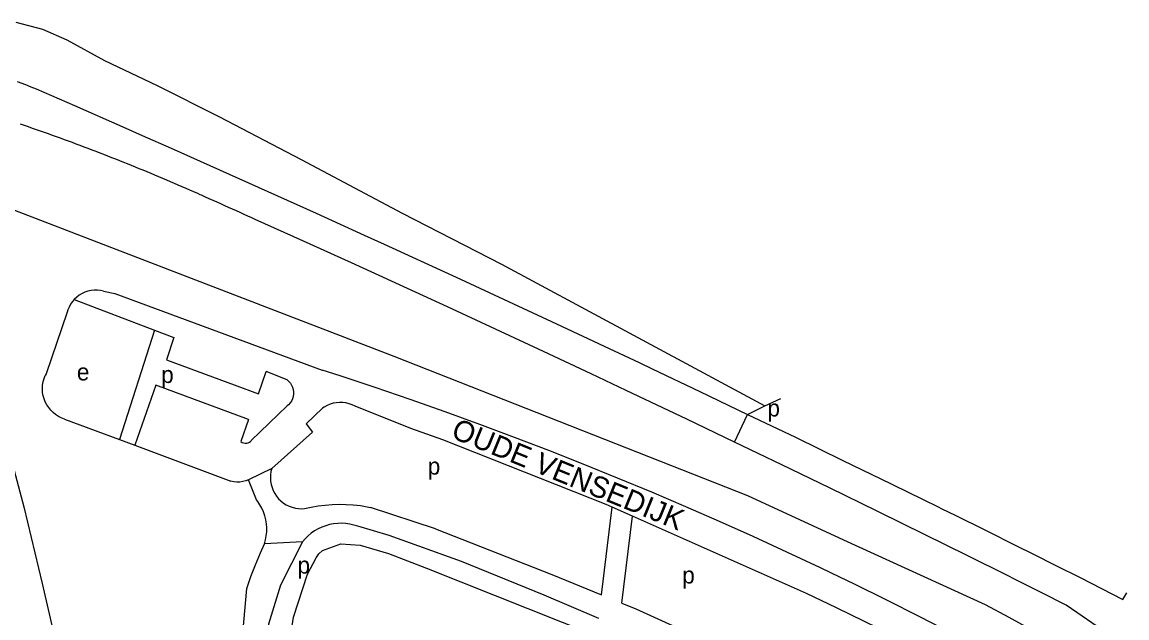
# Model space of a CAD drawing. Extents: x 157569 to 159501, y 382907 to 384670.
# Drawn here: x 157822.4 to 158083.4, y 384391.1 to 384531.9 of the extents above; entities that cross this region are included whole.
import ezdxf

# ---------------------------------------------------------------- set-up
doc = ezdxf.new("R2010")
doc.units = 0
for name, color, linetype in [('BLT_Basislijn', 7, 'Continuous'), ('BLT_Centroide', 7, 'Continuous'), ('BLT_Straatnaam', 7, 'Continuous'), ('BLT_Vlakafsluiter', 7, 'Continuous')]:
    doc.layers.add(name, color=color, linetype=linetype)

msp = doc.modelspace()

# ---------------------------------------------------------------- linework, layer by layer
at = {"layer": 'BLT_Basislijn'}
for p, q in [((157834.75, 384466.32), (157853.74, 384459.06)), ((157833.07, 384463.36), (157828.09, 384448.73)), ((157853.74, 384459.06), (157845.4, 384433.23)), ((157885.02, 384447.33), (157880.1, 384449.33)), ((157828.09, 384448.73), (157827.88, 384448.33)), ((157876.54, 384432.99), (157885.07, 384441.18)), ((157914.28, 384435.88), (157901.1, 384441.13)), ((157832.41, 384438.07), (157845.4, 384433.23)), ((157875.9, 384437.95), (157874.14, 384432.77)), ((157845.4, 384433.23), (157849.02, 384431.88)), ((157849.02, 384431.88), (157871.73, 384423.42)), ((157881.4, 384426.41), (157875.92, 384423.71)), ((157877.79, 384419.02), (157875.92, 384423.71)), ((157920.13, 384412.11), (157904.71, 384417.21)), ((157959.33, 384396.56), (157961.83, 384417.29)), ((157964.13, 384394.6), (157966.61, 384415.16)), ((157892.54, 384406.25), (157893.39, 384407.05)), ((157893.39, 384407.05), (157897.72, 384408.6)), ((157897.72, 384408.6), (157902.31, 384408.32)), ((157902.31, 384408.32), (157909.02, 384406.29)), ((157889.87, 384401.46), (157891.87, 384405.29)), ((157891.87, 384405.29), (157892.54, 384406.25)), ((157909.02, 384406.29), (157917.97, 384402.83)), ((157917.97, 384402.83), (157958.16, 384386.84)), ((157886.51, 384391.25), (157889.87, 384401.46)), ((157884.93, 384380.62), (157886.51, 384391.25))]:
    msp.add_line(p, q, dxfattribs=at)
for points in [[(157820.98, 384531.86), (157827.21, 384530.17), (157832.97, 384527.64), (157841.86, 384522.76), (157854.32, 384516.88), (157869.04, 384509.47), (157888.36, 384499.41), (157912.21, 384486.72), (157935.72, 384474.64), (157954.45, 384464.62), (157997.88, 384441.21)], [(157821.29, 384517.79), (157823.26, 384517.08), (157824.5, 384516.6), (157825.73, 384516.08), (157834.77, 384512.14), (157846.21, 384507.11), (157850.77, 384505.1), (157857.65, 384502.06), (157869.07, 384496.97), (157880.48, 384491.86), (157891.87, 384486.72), (157903.26, 384481.55), (157907.94, 384479.42), (157914.62, 384476.36), (157925.98, 384471.13), (157937.33, 384465.88), (157948.66, 384460.6), (157959.97, 384455.29), (157968.21, 384451.4), (157971.28, 384449.95), (157982.57, 384444.58), (157993.84, 384439.19)], [(157990.71, 384432.65), (157979.45, 384438.04), (157968.17, 384443.4), (157965.11, 384444.85), (157956.89, 384448.73), (157945.58, 384454.03), (157934.27, 384459.3), (157922.94, 384464.55), (157911.6, 384469.77), (157904.93, 384472.82), (157900.25, 384474.96), (157888.88, 384480.12), (157877.5, 384485.25), (157876.69, 384485.62), (157875.78, 384486.03), (157874.86, 384486.44), (157873.95, 384486.85), (157873.04, 384487.25), (157872.13, 384487.66), (157871.21, 384488.07), (157870.3, 384488.48), (157869.39, 384488.89), (157868.48, 384489.3), (157867.56, 384489.71), (157866.65, 384490.11), (157865.74, 384490.52), (157864.82, 384490.93), (157864.53, 384491.06), (157863.91, 384491.34), (157863, 384491.74), (157862.08, 384492.14), (157861.17, 384492.55), (157860.25, 384492.94), (157859.33, 384493.34), (157858.42, 384493.74), (157857.5, 384494.13), (157856.58, 384494.52), (157855.66, 384494.91), (157854.74, 384495.3), (157853.82, 384495.69), (157852.9, 384496.07), (157851.97, 384496.46), (157851.05, 384496.84), (157850.12, 384497.22), (157849.2, 384497.59), (157848.27, 384497.97), (157847.35, 384498.34), (157846.42, 384498.72), (157845.49, 384499.09), (157844.56, 384499.45), (157843.63, 384499.82), (157842.7, 384500.18), (157841.77, 384500.55), (157840.84, 384500.91), (157839.91, 384501.27), (157838.97, 384501.62), (157838.04, 384501.98), (157837.1, 384502.33), (157836.17, 384502.68), (157835.23, 384503.03), (157834.3, 384503.38), (157833.36, 384503.73), (157832.42, 384504.07), (157831.48, 384504.41), (157830.54, 384504.75), (157829.6, 384505.09), (157828.66, 384505.43), (157827.72, 384505.76), (157826.78, 384506.09), (157825.83, 384506.42), (157824.89, 384506.75), (157823.95, 384507.08), (157823, 384507.4), (157822.05, 384507.73)], [(158016.56, 384409.49), (157993.85, 384419.91), (157910.36, 384452.84), (157802.79, 384494.17)], [(157785.74, 384491.86), (157791.37, 384485.49), (157798.02, 384479.29), (157802.69, 384474.1), (157806.4, 384468.47), (157808.82, 384463.57), (157811.76, 384455.2), (157818.57, 384433.33), (157822.82, 384417.31), (157827.2, 384399.26), (157830.67, 384383.83), (157833.54, 384367.87), (157836.35, 384353.29), (157840.01, 384327.2), (157843.02, 384303.79), (157845.24, 384278.94), (157848.12, 384253.31), (157853.68, 384220.02), (157857.08, 384190.66), (157860.08, 384150.97), (157861.78, 384102.06), (157861.78, 384049.75), (157865.23, 384042.81)], [(157841.67, 384468.25), (157840.94, 384468.41), (157840.2, 384468.49), (157839.45, 384468.49), (157838.71, 384468.41), (157837.98, 384468.25), (157837.27, 384468.02), (157836.59, 384467.71), (157835.94, 384467.33), (157835.34, 384466.88), (157834.75, 384466.32)], [(157841.67, 384468.25), (157844.36, 384467.75), (157893.31, 384449.63)], [(157834.75, 384466.32), (157834.3, 384465.81), (157833.88, 384465.2), (157833.52, 384464.54), (157833.23, 384463.85), (157833.07, 384463.36)], [(157853.74, 384459.06), (157858.24, 384457.34), (157856.5, 384452.04), (157878.28, 384444.05), (157880.1, 384449.33)], [(158015.76, 384400.64), (158011.02, 384402.93), (158003.12, 384406.64), (157995.18, 384410.29), (157987.21, 384413.86), (157979.21, 384417.36), (157971.18, 384420.78), (157963.11, 384424.13), (157955.02, 384427.41), (157946.89, 384430.61), (157938.74, 384433.74), (157930.56, 384436.79), (157922.35, 384439.77), (157914.12, 384442.68), (157905.85, 384445.5), (157897.56, 384448.26), (157893.31, 384449.63)], [(157832.41, 384438.07), (157831.69, 384438.35), (157830.99, 384438.71), (157830.34, 384439.13), (157829.74, 384439.62), (157829.19, 384440.17), (157828.7, 384440.77), (157828.27, 384441.42), (157827.91, 384442.11), (157827.62, 384442.83), (157827.41, 384443.58), (157827.28, 384444.34), (157827.23, 384445.12), (157827.25, 384445.9), (157827.36, 384446.67), (157827.55, 384447.42), (157827.81, 384448.15), (157827.88, 384448.33)], [(157885.02, 384447.33), (157885.44, 384446.97), (157885.8, 384446.55), (157886.1, 384446.08), (157886.33, 384445.57), (157886.48, 384445.03), (157886.55, 384444.48), (157886.55, 384443.93), (157886.47, 384443.38), (157886.3, 384442.84), (157886.07, 384442.34), (157885.76, 384441.87), (157885.39, 384441.46), (157885.07, 384441.18)], [(157875.9, 384437.95), (157854.02, 384446.1), (157849.02, 384431.88)], [(157901.1, 384441.13), (157900.4, 384441.46), (157899.68, 384441.71), (157898.94, 384441.89), (157898.18, 384441.98), (157897.42, 384442), (157896.66, 384441.94), (157895.9, 384441.79), (157895.17, 384441.57), (157894.47, 384441.28), (157893.8, 384440.91), (157893.42, 384440.66)], [(157893.42, 384440.66), (157889.56, 384436.95), (157891.02, 384435.01), (157881.4, 384426.41)], [(157993.84, 384439.19), (158005.11, 384433.76), (158016.36, 384428.31), (158027.59, 384422.83), (158028.09, 384422.59), (158038.82, 384417.33), (158039.75, 384416.87), (158042.83, 384415.35), (158050.03, 384411.79), (158057.55, 384408.05), (158061.22, 384406.22), (158066.64, 384403.5), (158072.39, 384400.61), (158082.51, 384395.46), (158083.44, 384397)], [(157961.83, 384417.29), (157960.43, 384417.91), (157921.84, 384433.19), (157914.28, 384435.88)], [(157874.14, 384432.77), (157874.43, 384432.56), (157874.77, 384432.42), (157875.13, 384432.36), (157875.49, 384432.38), (157875.85, 384432.47), (157876.17, 384432.64), (157876.45, 384432.88), (157876.54, 384432.99)], [(158078.9, 384387.37), (158069.12, 384394.13), (158063.38, 384397.02), (158057.97, 384399.73), (158054.32, 384401.56), (158046.81, 384405.29), (158039.63, 384408.84), (158036.55, 384410.36), (158035.61, 384410.82), (158024.91, 384416.08), (158024.41, 384416.32), (158013.19, 384421.79), (158001.95, 384427.24), (157990.71, 384432.65)], [(157881.4, 384426.41), (157881.21, 384425.67), (157881.11, 384424.91), (157881.08, 384424.14), (157881.13, 384423.37), (157881.26, 384422.62), (157881.47, 384421.88), (157881.76, 384421.17), (157882.11, 384420.49), (157882.54, 384419.85), (157883.03, 384419.26), (157883.58, 384418.72), (157884.18, 384418.24), (157884.83, 384417.83), (157885.52, 384417.49), (157886.24, 384417.22), (157886.98, 384417.03), (157887.74, 384416.92), (157888.51, 384416.88), (157889.12, 384416.91)], [(157875.92, 384423.71), (157875.27, 384423.46), (157874.58, 384423.29), (157873.89, 384423.2), (157873.18, 384423.18), (157872.48, 384423.25), (157871.73, 384423.42)], [(157879.71, 384408.61), (157879.96, 384409.54), (157880.12, 384410.48), (157880.21, 384411.43), (157880.21, 384412.39), (157880.14, 384413.34), (157879.98, 384414.28), (157879.75, 384415.21), (157879.44, 384416.12), (157879.06, 384416.99), (157878.6, 384417.83), (157878.08, 384418.63), (157877.79, 384419.02)], [(157889.12, 384416.91), (157890.74, 384417.28), (157892.38, 384417.57), (157894.03, 384417.77), (157895.69, 384417.9), (157897.36, 384417.95), (157899.02, 384417.92), (157900.68, 384417.81), (157902.34, 384417.62), (157903.98, 384417.35), (157904.71, 384417.21)], [(157966.61, 384415.16), (157961.83, 384417.29)], [(158014.83, 384393.46), (158007.74, 384396.9), (157966.61, 384415.16)], [(157901.73, 384412.74), (157900.81, 384413.03), (157899.87, 384413.25), (157898.92, 384413.39), (157897.95, 384413.44), (157896.99, 384413.42), (157896.03, 384413.31), (157895.08, 384413.13), (157894.15, 384412.87), (157893.25, 384412.54), (157892.37, 384412.12), (157891.54, 384411.65), (157890.74, 384411.1), (157890, 384410.48), (157889.3, 384409.81), (157888.68, 384409.1)], [(157958.65, 384390.95), (157945.76, 384396.47), (157926.22, 384404.44), (157909.14, 384410.6), (157901.73, 384412.74)], [(157920.13, 384412.11), (157947.59, 384401.37), (157959.33, 384396.56)], [(157875.48, 384398.01), (157876.49, 384400.85), (157877.59, 384403.67), (157878.75, 384406.46), (157879.71, 384408.61)], [(157888.68, 384409.1), (157883.51, 384398.87), (157880.61, 384389.64), (157876.76, 384354.77)], [(158050, 384394.15), (158016.56, 384409.49)], [(158050, 384383.27), (158042.28, 384387.34), (158034.52, 384391.34), (158026.72, 384395.28), (158018.89, 384399.14), (158015.76, 384400.64)], [(157863.91, 384240.67), (157870.85, 384345.95), (157875.48, 384398.01)], [(157964.13, 384394.6), (157967.46, 384393.24), (158008.69, 384374.53)], [(158078.31, 384378.67), (158055.65, 384391.23), (158050, 384394.15)], [(158050, 384375.71), (158034.7, 384383.81), (158014.83, 384393.46)]]:
    msp.add_lwpolyline(points, dxfattribs=at)
at = {"layer": 'BLT_Vlakafsluiter'}
for p, q in [((157993.84, 384439.19), (157997.88, 384441.21)), ((157997.88, 384441.21), (158001.72, 384442.95)), ((157990.71, 384432.65), (157993.84, 384439.19)), ((157888.68, 384409.1), (157879.71, 384408.61))]:
    msp.add_line(p, q, dxfattribs=at)

# ---------------------------------------------------------------- texts
at = {"layer": 'BLT_Centroide'}
for s, p in [('e', (157835.36, 384447.2)), ('p', (157855.26, 384446.59)), ('p', (157998.5, 384438.67)), ('p', (157918.25, 384424.95)), ('p', (157887.48, 384401.56)), ('p', (157978.38, 384399.22))]:
    msp.add_text(s, height=4, dxfattribs=at).set_placement(p)
at = {"layer": 'BLT_Straatnaam'}
msp.add_text('OUDE VENSEDIJK', height=5, rotation=337.7482, dxfattribs=at).set_placement((157923.52, 384433.76))

doc.saveas('drawing.dxf')
